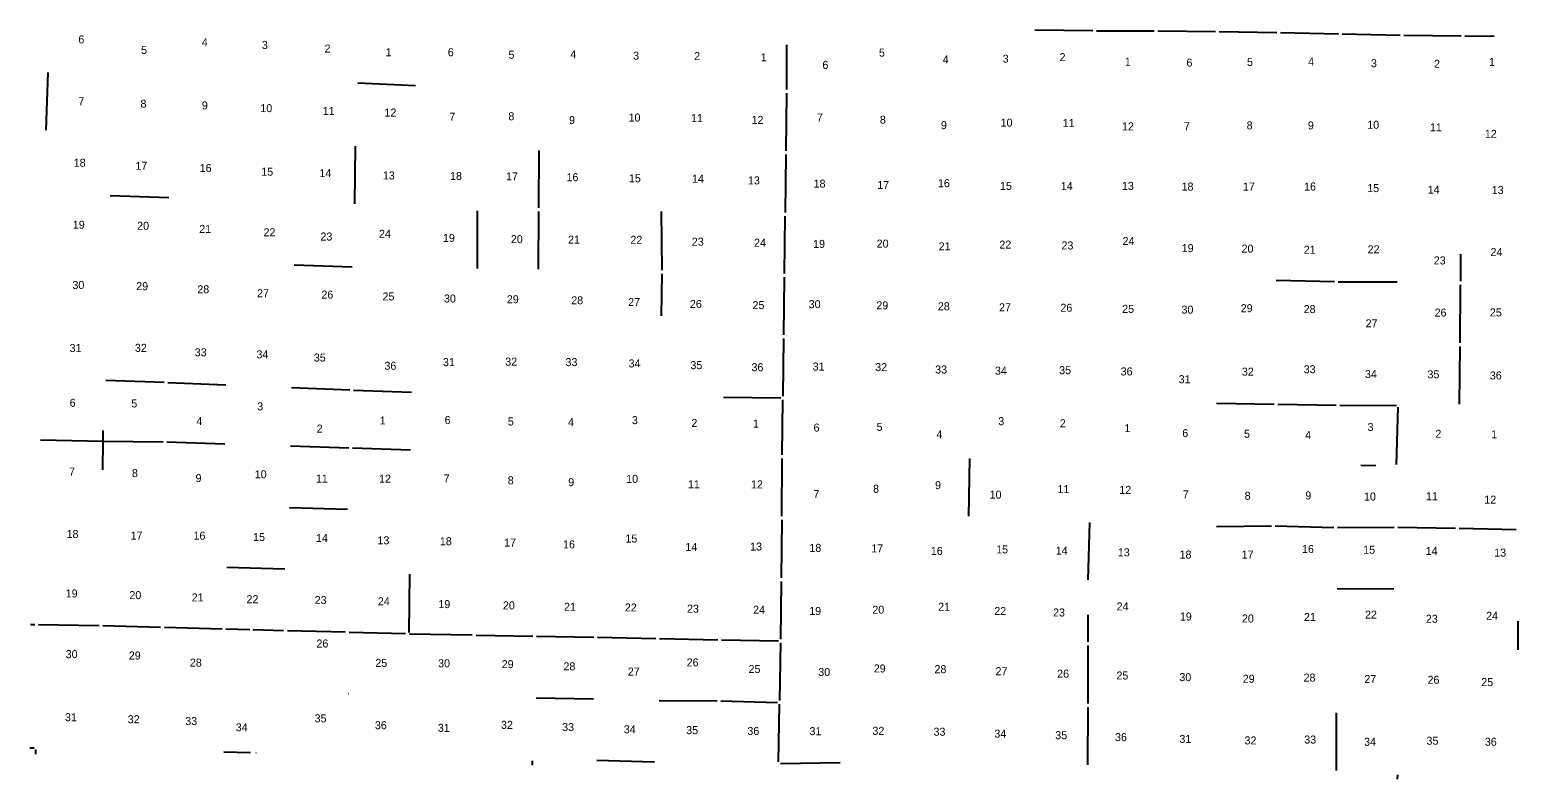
# Model space of a CAD drawing. Extents: x -2933025 to 31692252, y -2344676 to 23854604.
# Drawn here: x -2647962 to -2520318, y -2334760 to -2270540 of the extents above; entities that cross this region are included whole.
import ezdxf

# ---------------------------------------------------------------- set-up
doc = ezdxf.new("R2010")
doc.units = 0
doc.layers.add('tdCoSectLinePart', color=7, linetype='Continuous')
doc.layers.add('tdCoSectNmbr', color=7, linetype='Continuous')

msp = doc.modelspace()

# ---------------------------------------------------------------- linework, layer by layer
at = {"layer": 'tdCoSectLinePart'}
msp.add_line((-2578463, -2333356), (-2583592, -2333432), dxfattribs=at)
for points in [[(-2561768, -2270540), (-2556801, -2270614)], [(-2556484, -2270617), (-2551540, -2270637)], [(-2551224, -2270639), (-2546271, -2270686)], [(-2545954, -2270690), (-2541010, -2270773)], [(-2540694, -2270779), (-2535723, -2270889)], [(-2583071, -2271832), (-2583080, -2275646)], [(-2535406, -2270896), (-2530456, -2270988)], [(-2530140, -2270993), (-2525200, -2271062)], [(-2524883, -2271066), (-2522389, -2271092)], [(-2646549, -2279148), (-2646382, -2274200)], [(-2619826, -2275094), (-2614870, -2275326)], [(-2583082, -2275962), (-2583120, -2280923)], [(-2620080, -2285462), (-2620027, -2280507)], [(-2604293, -2285794), (-2604291, -2280875)], [(-2583123, -2281239), (-2583174, -2286184)], [(-2641054, -2284741), (-2636042, -2284922)], [(-2609574, -2290987), (-2609571, -2286055)], [(-2604331, -2291043), (-2604295, -2286110)], [(-2593744, -2291149), (-2593782, -2286104)], [(-2583239, -2291429), (-2583177, -2286501)], [(-2525253, -2292081), (-2525234, -2289757)], [(-2625293, -2290674), (-2620326, -2290866)], [(-2593783, -2295055), (-2593744, -2291465)], [(-2583309, -2296672), (-2583243, -2291748)], [(-2541080, -2291989), (-2536082, -2292121)], [(-2535765, -2292125), (-2530709, -2292142)], [(-2525285, -2297354), (-2525256, -2292398)], [(-2583313, -2296989), (-2583383, -2301938)], [(-2525342, -2302634), (-2525288, -2297671)], [(-2641429, -2300554), (-2636439, -2300738)], [(-2636122, -2300751), (-2631138, -2300969)], [(-2625521, -2301195), (-2620529, -2301397)], [(-2620213, -2301409), (-2615220, -2301584)], [(-2588460, -2302016), (-2583544, -2302093)], [(-2583427, -2306973), (-2583387, -2302254)], [(-2546188, -2302527), (-2541242, -2302612)], [(-2540925, -2302618), (-2535938, -2302709)], [(-2535621, -2302713), (-2530744, -2302736)], [(-2530755, -2307778), (-2530608, -2302877)], [(-2641671, -2305791), (-2641656, -2304870)], [(-2647049, -2305673), (-2641671, -2305791)], [(-2641687, -2308249), (-2641671, -2305791)], [(-2641671, -2305791), (-2636517, -2305852)], [(-2636200, -2305859), (-2631224, -2306021)], [(-2625613, -2306193), (-2620612, -2306360)], [(-2620295, -2306371), (-2615309, -2306543)], [(-2583460, -2312227), (-2583429, -2307290)], [(-2567435, -2312210), (-2567339, -2307265)], [(-2533823, -2307847), (-2532532, -2307884)], [(-2625688, -2311476), (-2620703, -2311621)], [(-2583463, -2312543), (-2583520, -2317495)], [(-2557200, -2317682), (-2557052, -2312774)], [(-2546204, -2313111), (-2541482, -2313036)], [(-2541164, -2313038), (-2536127, -2313191)], [(-2535810, -2313194), (-2530952, -2313168)], [(-2530635, -2313170), (-2525697, -2313242)], [(-2525380, -2313248), (-2520481, -2313360)], [(-2631065, -2316600), (-2626075, -2316746)], [(-2615424, -2322195), (-2615383, -2317188)], [(-2583524, -2317811), (-2583588, -2322758)], [(-2535843, -2318431), (-2530974, -2318451)], [(-2647890, -2321503), (-2647521, -2321511)], [(-2647204, -2321516), (-2642014, -2321587)], [(-2641697, -2321593), (-2636740, -2321729)], [(-2636422, -2321737), (-2631471, -2321866)], [(-2557190, -2322986), (-2557197, -2320665)], [(-2520328, -2323672), (-2520318, -2321221)], [(-2631153, -2321874), (-2629083, -2321931)], [(-2628845, -2321938), (-2626196, -2322011)], [(-2625864, -2322019), (-2620902, -2322143)], [(-2620586, -2322151), (-2615728, -2322283)], [(-2615399, -2322292), (-2610012, -2322400)], [(-2609695, -2322406), (-2604809, -2322494)], [(-2604493, -2322500), (-2599578, -2322590)], [(-2599263, -2322596), (-2594264, -2322696)], [(-2593948, -2322703), (-2588968, -2322804)], [(-2588651, -2322811), (-2583748, -2322912)], [(-2583592, -2323074), (-2583670, -2328019)], [(-2557187, -2328262), (-2557190, -2323303)], [(-2620636, -2327420), (-2620609, -2327421)], [(-2604546, -2327775), (-2599621, -2327876)], [(-2593998, -2328007), (-2589013, -2328049)], [(-2588697, -2328054), (-2583831, -2328173)], [(-2583748, -2333273), (-2583675, -2328336)], [(-2557226, -2333540), (-2557188, -2328579)], [(-2535909, -2334007), (-2535908, -2329065)], [(-2647962, -2332061), (-2647586, -2332073)], [(-2647442, -2332605), (-2647437, -2332222)], [(-2631310, -2332416), (-2629036, -2332475)], [(-2628584, -2332486), (-2628547, -2332487)], [(-2604845, -2333545), (-2604840, -2333174)], [(-2599347, -2333133), (-2594391, -2333268)], [(-2530679, -2334760), (-2530647, -2334393)]]:
    msp.add_lwpolyline(points, dxfattribs=at)

# ---------------------------------------------------------------- texts
at = {"layer": 'tdCoSectNmbr'}
for s, height, rotation, p in [('6', 686, 359.94474, (-2643796, -2271706)), ('5', 686, 359.94552, (-2638418, -2272611)), ('4', 686, 359.94627, (-2633208, -2271946)), ('3', 686, 359.94701, (-2628057, -2272181)), ('2', 686, 359.94779, (-2622683, -2272493)), ('1', 686, 359.94854, (-2617444, -2272805)), ('6', 686, 359.94931, (-2612118, -2272809)), ('5', 686, 359.95006, (-2606914, -2273019)), ('4', 686, 359.95122, (-2601608, -2272981)), ('3', 686, 359.952, (-2596218, -2273097)), ('2', 686, 359.95275, (-2590986, -2273135)), ('1', 686, 359.95357, (-2585275, -2273239)), ('6', 686, 359.95433, (-2579988, -2273893)), ('5', 686, 359.95504, (-2575134, -2272836)), ('4', 686, 359.95583, (-2569666, -2273418)), ('3', 686, 359.95657, (-2564529, -2273361)), ('2', 686, 359.95727, (-2559651, -2273227)), ('1', 686, 359.95807, (-2554056, -2273618)), ('6', 686, 359.95884, (-2548771, -2273696)), ('5', 686, 359.95959, (-2543576, -2273635)), ('4', 686, 359.96035, (-2538334, -2273612)), ('3', 686, 359.96071, (-2532949, -2273748)), ('2', 686, 359.96149, (-2527541, -2273798)), ('1', 686, 359.96224, (-2522821, -2273630)), ('7', 686, 359.94477, (-2643801, -2277005)), ('8', 686, 359.94554, (-2638468, -2277213)), ('9', 686, 359.9463, (-2633203, -2277361)), ('10', 686.4, 359.94704, (-2628190, -2277596)), ('11', 686.4, 359.94781, (-2622836, -2277831)), ('12', 686.4, 359.94858, (-2617545, -2277971)), ('7', 686, 359.94936, (-2611979, -2278327)), ('8', 686, 359.95009, (-2606919, -2278291)), ('9', 686, 359.95122, (-2601718, -2278622)), ('10', 686.4, 359.95197, (-2596614, -2278401)), ('11', 686.4, 359.95274, (-2591253, -2278445)), ('12', 686.4, 359.95349, (-2586067, -2278605)), ('7', 686, 359.95428, (-2580465, -2278406)), ('8', 686, 359.95506, (-2575064, -2278585)), ('9', 686, 359.95582, (-2569824, -2279053)), ('10', 686.4, 359.95658, (-2564706, -2278843)), ('11', 686.4, 359.95733, (-2559387, -2278875)), ('8', 686, 359.9596, (-2543607, -2279071)), ('9', 686, 359.96035, (-2538355, -2279077)), ('10', 686.4, 359.96058, (-2533263, -2279022)), ('12', 686.4, 359.95808, (-2554299, -2279159)), ('7', 686, 359.95882, (-2548985, -2279149)), ('11', 686.4, 359.96134, (-2527893, -2279241)), ('12', 686.4, 359.96204, (-2523180, -2279795)), ('18', 686.4, 359.94476, (-2644192, -2282273)), ('17', 686.4, 359.94553, (-2638900, -2282536)), ('16', 686.4, 359.94632, (-2633392, -2282727)), ('15', 686.4, 359.94708, (-2628115, -2283045)), ('14', 686.4, 359.9478, (-2623121, -2283168)), ('13', 686.4, 359.94859, (-2617682, -2283366)), ('18', 686.4, 359.94939, (-2611922, -2283408)), ('17', 686.4, 359.95011, (-2607121, -2283440)), ('16', 686.4, 359.95122, (-2601933, -2283513)), ('15', 686.4, 359.95199, (-2596577, -2283602)), ('14', 686.4, 359.95277, (-2591175, -2283644)), ('13', 686.4, 359.95346, (-2586376, -2283789)), ('18', 686.4, 359.95428, (-2580744, -2284063)), ('17', 686.4, 359.95506, (-2575284, -2284182)), ('16', 686.4, 359.95581, (-2570084, -2284028)), ('15', 686.4, 359.95658, (-2564758, -2284262)), ('14', 686.4, 359.95733, (-2559545, -2284275)), ('13', 686.4, 359.95809, (-2554305, -2284260)), ('18', 686.4, 359.95882, (-2549187, -2284315)), ('17', 686.4, 359.95958, (-2543931, -2284317)), ('16', 686.4, 359.96034, (-2538683, -2284314)), ('15', 686.4, 359.96047, (-2533270, -2284449)), ('14', 686.4, 359.96122, (-2528077, -2284577)), ('13', 686.4, 359.96201, (-2522592, -2284615)), ('19', 686.4, 359.94478, (-2644272, -2287584)), ('20', 686.4, 359.94558, (-2638754, -2287676)), ('21', 686.4, 359.94634, (-2633430, -2287949)), ('22', 686.4, 359.94714, (-2627917, -2288233)), ('23', 686.4, 359.94784, (-2623036, -2288597)), ('24', 686.4, 359.94857, (-2618018, -2288367)), ('19', 686.4, 359.94936, (-2612532, -2288714)), ('20', 686.4, 359.9502, (-2606705, -2288824)), ('21', 686.4, 359.95124, (-2601807, -2288862)), ('22', 686.4, 359.95202, (-2596454, -2288880)), ('23', 686.4, 359.95278, (-2591186, -2289043)), ('24', 686.4, 359.95355, (-2585853, -2289129)), ('19', 686.4, 359.95428, (-2580786, -2289228)), ('20', 686.4, 359.95507, (-2575333, -2289206)), ('22', 686.4, 359.95658, (-2564815, -2289287)), ('23', 686.4, 359.95735, (-2559488, -2289361)), ('24', 686.4, 359.95811, (-2554249, -2288983)), ('21', 686.4, 359.95583, (-2570019, -2289441)), ('19', 686.4, 359.95884, (-2549176, -2289593)), ('20', 686.4, 359.95958, (-2544045, -2289635)), ('21', 686.4, 359.96034, (-2538712, -2289733)), ('22', 686.4, 359.96036, (-2533234, -2289695)), ('24', 686.4, 359.96188, (-2522694, -2289929)), ('23', 686.4, 359.96116, (-2527564, -2290646)), ('30', 686.4, 359.94477, (-2644305, -2292751)), ('29', 686.4, 359.94559, (-2638835, -2292851)), ('28', 686.4, 359.94635, (-2633594, -2293116)), ('27', 686.4, 359.94712, (-2628473, -2293458)), ('26', 686.4, 359.94788, (-2622959, -2293573)), ('25', 686.4, 359.94864, (-2617714, -2293734)), ('30', 686.4, 359.9494, (-2612444, -2293910)), ('29', 686.4, 359.95018, (-2607050, -2293975)), ('28', 686.4, 359.9513, (-2601527, -2294062)), ('27', 686.4, 359.95201, (-2596644, -2294212)), ('26', 686.4, 359.95277, (-2591353, -2294376)), ('30', 686.4, 359.95427, (-2581166, -2294393)), ('25', 686.4, 359.95354, (-2585983, -2294477)), ('29', 686.4, 359.95508, (-2575364, -2294493)), ('28', 686.4, 359.95584, (-2570088, -2294575)), ('27', 686.4, 359.95659, (-2564838, -2294662)), ('26', 686.4, 359.95735, (-2559581, -2294704)), ('25', 686.4, 359.95811, (-2554280, -2294801)), ('30', 686.4, 359.95885, (-2549195, -2294861)), ('29', 686.4, 359.95958, (-2544115, -2294740)), ('28', 686.4, 359.96036, (-2538720, -2294818)), ('26', 686.4, 359.96108, (-2527489, -2295115)), ('25', 686.4, 359.96177, (-2522753, -2295104)), ('27', 686.4, 359.96021, (-2533406, -2296039)), ('31', 686.4, 359.94479, (-2644548, -2298154)), ('32', 686.4, 359.94556, (-2638947, -2298139)), ('33', 686.4, 359.94634, (-2633819, -2298519)), ('34', 686.4, 359.94711, (-2628526, -2298697)), ('35', 686.4, 359.94782, (-2623603, -2298970)), ('31', 686.4, 359.94941, (-2612531, -2299364)), ('32', 686.4, 359.95018, (-2607188, -2299316)), ('33', 686.4, 359.95125, (-2602018, -2299360)), ('34', 686.4, 359.95203, (-2596611, -2299473)), ('36', 686.4, 359.94869, (-2617548, -2299674)), ('35', 686.4, 359.95279, (-2591308, -2299621)), ('36', 686.4, 359.95354, (-2586068, -2299799)), ('31', 686.4, 359.95429, (-2580826, -2299741)), ('32', 686.4, 359.95507, (-2575461, -2299789)), ('33', 686.4, 359.95581, (-2570320, -2299994)), ('34', 686.4, 359.95655, (-2565194, -2300096)), ('35', 686.4, 359.95734, (-2559688, -2300054)), ('36', 686.4, 359.95811, (-2554414, -2300159)), ('31', 686.4, 359.95882, (-2549437, -2300824)), ('32', 686.4, 359.9596, (-2544022, -2300180)), ('33', 686.4, 359.96037, (-2538714, -2299972)), ('34', 686.4, 359.96011, (-2533465, -2300384)), ('35', 686.4, 359.96088, (-2528101, -2300408)), ('36', 686.4, 359.96166, (-2522753, -2300504)), ('6', 686, 359.94481, (-2644538, -2302847)), ('5', 686, 359.94557, (-2639253, -2302900)), ('3', 686, 359.94712, (-2628456, -2303158)), ('4', 686, 359.94638, (-2633675, -2304417)), ('1', 686, 359.94863, (-2617955, -2304355)), ('6', 686, 359.94944, (-2612388, -2304325)), ('5', 686, 359.95022, (-2606969, -2304447)), ('4', 686, 359.95127, (-2601802, -2304503)), ('3', 686, 359.95203, (-2596324, -2304333)), ('2', 686, 359.95279, (-2591228, -2304577)), ('1', 686, 359.95355, (-2585949, -2304627)), ('3', 686, 359.95657, (-2564907, -2304422)), ('2', 686, 359.95734, (-2559628, -2304605)), ('2', 686, 359.94789, (-2623363, -2305057)), ('6', 686, 359.9543, (-2580748, -2304970)), ('5', 686, 359.95508, (-2575338, -2304909)), ('4', 686, 359.95582, (-2570212, -2305544)), ('1', 686, 359.95809, (-2554087, -2305018)), ('6', 686, 359.95886, (-2549125, -2305446)), ('5', 686, 359.95962, (-2543835, -2305502)), ('4', 686, 359.96038, (-2538588, -2305606)), ('3', 686, 359.96003, (-2533238, -2304914)), ('2', 686, 359.96086, (-2527423, -2305503)), ('1', 686, 359.96154, (-2522638, -2305545)), ('7', 686, 359.94483, (-2644592, -2308736)), ('8', 686, 359.94561, (-2639199, -2308872)), ('9', 686, 359.94639, (-2633748, -2309297)), ('10', 686.4, 359.94714, (-2628665, -2308970)), ('11', 686.4, 359.94789, (-2623426, -2309340)), ('12', 686.4, 359.94868, (-2618008, -2309345)), ('7', 686, 359.94946, (-2612466, -2309322)), ('8', 686, 359.95025, (-2606976, -2309492)), ('9', 686, 359.95128, (-2601789, -2309650)), ('10', 686.4, 359.95202, (-2596818, -2309365)), ('11', 686.4, 359.95278, (-2591525, -2309827)), ('12', 686.4, 359.95356, (-2586118, -2309841)), ('7', 686, 359.95432, (-2580760, -2310660)), ('8', 686, 359.95505, (-2575643, -2310217)), ('9', 686, 359.95587, (-2570327, -2309903)), ('10', 686.4, 359.95659, (-2565649, -2310716)), ('11', 686.4, 359.95734, (-2559831, -2310240)), ('12', 686.4, 359.95811, (-2554526, -2310306)), ('7', 686, 359.95888, (-2549082, -2310691)), ('8', 686, 359.95964, (-2543777, -2310813)), ('9', 686, 359.96039, (-2538579, -2310785)), ('10', 686.4, 359.95988, (-2533547, -2310881)), ('11', 686.4, 359.96064, (-2528229, -2310857)), ('12', 686.4, 359.96137, (-2523226, -2311146)), ('18', 686.4, 359.94485, (-2644805, -2314086)), ('17', 686.4, 359.94564, (-2639319, -2314226)), ('16', 686.4, 359.94642, (-2633920, -2314233)), ('15', 686.4, 359.94715, (-2628811, -2314349)), ('14', 686.4, 359.94793, (-2623416, -2314431)), ('13', 686.4, 359.94869, (-2618150, -2314631)), ('18', 686.4, 359.94946, (-2612797, -2314706)), ('17', 686.4, 359.95025, (-2607283, -2314827)), ('15', 686.4, 359.95202, (-2596883, -2314481)), ('16', 686.4, 359.95126, (-2602231, -2314983)), ('14', 686.4, 359.95277, (-2591740, -2315204)), ('13', 686.4, 359.95356, (-2586188, -2315165)), ('18', 686.4, 359.9543, (-2581105, -2315279)), ('17', 686.4, 359.95506, (-2575805, -2315327)), ('16', 686.4, 359.9558, (-2570691, -2315541)), ('15', 686.4, 359.9566, (-2565090, -2315410)), ('14', 686.4, 359.95734, (-2559974, -2315507)), ('13', 686.4, 359.95811, (-2554652, -2315664)), ('18', 686.4, 359.95887, (-2549361, -2315851)), ('17', 686.4, 359.95964, (-2544036, -2315851)), ('16', 686.4, 359.96038, (-2538863, -2315377)), ('15', 686.4, 359.95978, (-2533614, -2315438)), ('14', 686.4, 359.96055, (-2528260, -2315546)), ('13', 686.4, 359.9614, (-2522380, -2315686)), ('19', 686.4, 359.94487, (-2644880, -2319182)), ('20', 686.4, 359.94566, (-2639420, -2319326)), ('21', 686.4, 359.94642, (-2634074, -2319525)), ('22', 686.4, 359.9471, (-2629376, -2319675)), ('23', 686.4, 359.94794, (-2623532, -2319751)), ('24', 686.4, 359.94872, (-2618112, -2319856)), ('19', 686.4, 359.94947, (-2612923, -2320098)), ('20', 686.4, 359.95027, (-2607384, -2320209)), ('21', 686.4, 359.95128, (-2602147, -2320323)), ('22', 686.4, 359.95203, (-2596932, -2320386)), ('23', 686.4, 359.9528, (-2591598, -2320493)), ('24', 686.4, 359.95362, (-2585929, -2320574)), ('19', 686.4, 359.95431, (-2581120, -2320690)), ('20', 686.4, 359.95509, (-2575706, -2320580)), ('21', 686.4, 359.95584, (-2570067, -2320327)), ('22', 686.4, 359.95659, (-2565252, -2320687)), ('23', 686.4, 359.95732, (-2560209, -2320814)), ('24', 686.4, 359.9581, (-2554757, -2320302)), ('19', 686.4, 359.95888, (-2549334, -2321160)), ('21', 686.4, 359.96041, (-2538695, -2321203)), ('22', 686.4, 359.95969, (-2533461, -2320999)), ('24', 686.4, 359.96119, (-2523073, -2321100)), ('20', 686.4, 359.95965, (-2544013, -2321329)), ('23', 686.4, 359.96043, (-2528239, -2321355)), ('26', 686.4, 359.94795, (-2623380, -2323474)), ('30', 686.4, 359.9449, (-2644883, -2324386)), ('29', 686.4, 359.94568, (-2639470, -2324503)), ('26', 686.4, 359.95281, (-2591632, -2325094)), ('28', 686.4, 359.94643, (-2634233, -2325111)), ('25', 686.4, 359.94872, (-2618329, -2325138)), ('30', 686.4, 359.94949, (-2612946, -2325170)), ('29', 686.4, 359.95028, (-2607493, -2325244)), ('28', 686.4, 359.95129, (-2602194, -2325432)), ('27', 686.4, 359.95208, (-2596676, -2325880)), ('25', 686.4, 359.95357, (-2586323, -2325661)), ('30', 686.4, 359.95443, (-2580345, -2325914)), ('29', 686.4, 359.95512, (-2575582, -2325611)), ('28', 686.4, 359.95587, (-2570378, -2325673)), ('27', 686.4, 359.95662, (-2565143, -2325847)), ('26', 686.4, 359.95738, (-2559860, -2326060)), ('25', 686.4, 359.95811, (-2554777, -2326215)), ('30', 686.4, 359.95889, (-2549378, -2326355)), ('29', 686.4, 359.95967, (-2543942, -2326492)), ('28', 686.4, 359.96042, (-2538726, -2326394)), ('27', 686.4, 359.95956, (-2533516, -2326516)), ('26', 686.4, 359.96035, (-2528094, -2326583)), ('25', 686.4, 359.96101, (-2523491, -2326780)), ('31', 686.4, 359.94491, (-2644946, -2329792)), ('32', 686.4, 359.94569, (-2639562, -2329965)), ('33', 686.4, 359.9464, (-2634630, -2330114)), ('35', 686.4, 359.948, (-2623537, -2329887)), ('34', 686.4, 359.9471, (-2630297, -2330653)), ('36', 686.4, 359.94874, (-2618364, -2330476)), ('31', 686.4, 359.94951, (-2612967, -2330701)), ('32', 686.4, 359.9503, (-2607552, -2330443)), ('33', 686.4, 359.95128, (-2602309, -2330635)), ('34', 686.4, 359.95204, (-2597023, -2330824)), ('35', 686.4, 359.95281, (-2591673, -2330899)), ('36', 686.4, 359.95357, (-2586425, -2330968)), ('31', 686.4, 359.95433, (-2581094, -2330987)), ('32', 686.4, 359.95511, (-2575703, -2330958)), ('33', 686.4, 359.95587, (-2570461, -2331034)), ('34', 686.4, 359.95662, (-2565242, -2331199)), ('35', 686.4, 359.95737, (-2560022, -2331332)), ('36', 686.4, 359.95811, (-2554896, -2331495)), ('31', 686.4, 359.95889, (-2549373, -2331649)), ('32', 686.4, 359.95971, (-2543789, -2331778)), ('33', 686.4, 359.96044, (-2538670, -2331704)), ('34', 686.4, 359.95945, (-2533537, -2331896)), ('35', 686.4, 359.96022, (-2528185, -2331805)), ('36', 686.4, 359.96095, (-2523184, -2331892))]:
    msp.add_text(s, height=height, rotation=rotation, dxfattribs=at).set_placement(p)

doc.saveas('drawing.dxf')
